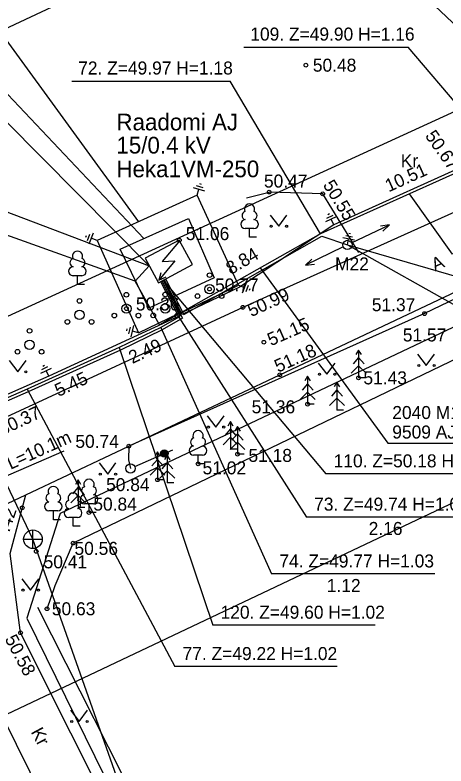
# Model space of a CAD drawing. Extents: x 642747 to 644424, y 6457048 to 6458238.
# Drawn here: x 643688.45 to 643711.66, y 6457504.01 to 6457544.44 of the extents above; entities that cross this region are included whole.
import ezdxf

# ---------------------------------------------------------------- set-up
doc = ezdxf.new("R2010")
doc.units = 0
for name, color, linetype in [('ABIJOONIS', 7, 'Continuous'), ('AED', 7, 'Continuous'), ('HALJASTUS', 7, 'Continuous'), ('HOONE', 7, 'Continuous'), ('JOONSIDE', 7, 'Continuous'), ('KKAEV', 7, 'Continuous'), ('KOORDPUNKT', 7, 'Continuous'), ('KORGUS', 7, 'Continuous'), ('KPKAABEL', 7, 'Continuous'), ('KTRASS', 7, 'Continuous'), ('MOOTPIIR', 7, 'Continuous'), ('MPKAABEL', 7, 'Continuous'), ('MPOHULIIN', 7, 'Continuous'), ('PIIR', 7, 'Continuous'), ('POST', 7, 'Continuous'), ('PUU', 7, 'Continuous'), ('SIOHULIIN', 7, 'Continuous'), ('SITRASS', 7, 'Continuous'), ('TEE', 7, 'Continuous')]:
    doc.layers.add(name, color=color, linetype=linetype)

msp = doc.modelspace()

# ---------------------------------------------------------------- linework, layer by layer
at = {"layer": 'ABIJOONIS'}
for points in [[(643698.673, 6457546.441), (643709.471, 6457546.441), (643717.684, 6457538.68)], [(643677.003, 6457543.321), (643687.801, 6457543.321), (643695.095, 6457533.303)], [(643676.957, 6457540.474), (643687.756, 6457540.474), (643695.388, 6457532.398)], [(643670.945, 6457535.902), (643677.673, 6457535.902), (643685.239, 6457534.889), (643695.681, 6457530.934)], [(643718.109, 6457534.067), (643712.004, 6457531.56), (643709.689, 6457534.812)], [(643706.35, 6457532.056), (643720.437, 6457527.98), (643731.397, 6457527.98)], [(643701.648, 6457530.817), (643708.517, 6457521.392), (643734.485, 6457521.392)], [(643691.073, 6457520.957), (643684.142, 6457517.967), (643682.39, 6457521.311)]]:
    msp.add_lwpolyline(points, dxfattribs=at)
at = {"layer": 'AED'}
for points in [[(643730.468, 6457534.795), (643729.228, 6457534.2), (643722.007, 6457530.651), (643691.577, 6457516.004)], [(643690.171, 6457512.47), (643690.611, 6457513.72), (643691.577, 6457516.004)]]:
    msp.add_lwpolyline(points, dxfattribs=at)
at = {"layer": 'HALJASTUS'}
for p, q in [((643702.185, 6457533.669), (643702.649, 6457533.062)), ((643702.649, 6457533.062), (643703.094, 6457533.669)), ((643710.127, 6457526.179), (643710.591, 6457525.572)), ((643710.591, 6457525.572), (643711.036, 6457526.179)), ((643688.134, 6457525.838), (643688.597, 6457525.231)), ((643688.597, 6457525.231), (643689.043, 6457525.838)), ((643704.779, 6457525.701), (643705.242, 6457525.094)), ((643705.242, 6457525.094), (643705.688, 6457525.701)), ((643698.796, 6457522.862), (643699.26, 6457522.255)), ((643699.26, 6457522.255), (643699.705, 6457522.862)), ((643692.977, 6457520.322), (643693.441, 6457519.716)), ((643693.441, 6457519.716), (643693.886, 6457520.322)), ((643688.815, 6457514.086), (643689.278, 6457513.479)), ((643689.278, 6457513.479), (643689.724, 6457514.086)), ((643691.438, 6457507.006), (643691.901, 6457506.4)), ((643691.901, 6457506.4), (643692.347, 6457507.006))]:
    msp.add_line(p, q, dxfattribs=at)
msp.add_lwpolyline([(643689.657, 6457512.556), (643695.741, 6457500.542), (643701.116, 6457489.232)], dxfattribs=at)
for centre in [(643702.248, 6457533.062), (643703.076, 6457533.062), (643710.19, 6457525.572), (643711.018, 6457525.572), (643689.025, 6457525.231), (643704.841, 6457525.094), (643705.67, 6457525.094), (643698.859, 6457522.255), (643699.687, 6457522.255), (643693.04, 6457519.716), (643693.868, 6457519.716), (643688.877, 6457513.479), (643689.706, 6457513.479), (643691.5, 6457506.4), (643692.329, 6457506.4)]:
    msp.add_circle(centre, 0.055, dxfattribs=at)
at = {"layer": 'HOONE'}
for p, q in [((643697.256, 6457532.202), (643696.375, 6457531.158)), ((643697.059, 6457531.201), (643696.195, 6457530.166)), ((643696.375, 6457531.158), (643697.059, 6457531.201)), ((643696.301, 6457530.548), (643696.195, 6457530.166)), ((643696.195, 6457530.166), (643696.584, 6457530.332))]:
    msp.add_line(p, q, dxfattribs=at)
msp.add_lwpolyline([(643697.295, 6457532.318), (643695.463, 6457531.343), (643696.167, 6457530.021), (643697.999, 6457530.996), (643697.295, 6457532.318)], dxfattribs=at)
at = {"layer": 'KKAEV'}
for p, q in [((643689.411, 6457515.713), (643689.411, 6457516.713)), ((643688.911, 6457516.213), (643689.911, 6457516.213))]:
    msp.add_line(p, q, dxfattribs=at)
msp.add_circle((643689.411, 6457516.213), 0.5, dxfattribs=at)
at = {"layer": 'KOORDPUNKT'}
for p, q in [((643700.769, 6457542.709), (643709.624, 6457542.709)), ((643714.481, 6457536.971), (643709.624, 6457542.709)), ((643691.5, 6457540.883), (643700.04, 6457540.883)), ((643704.897, 6457532.652), (643700.04, 6457540.883)), ((643695.681, 6457530.934), (643687.945, 6457538.712)), ((643694.912, 6457530.116), (643686.074, 6457533.275)), ((643706.35, 6457532.056), (643717.34, 6457525.878)), ((643696.422, 6457530.156), (643705.188, 6457519.734)), ((643697.272, 6457528.173), (643704.137, 6457517.404)), ((643696.304, 6457527.618), (643702.265, 6457514.344)), ((643694.061, 6457526.533), (643699.098, 6457511.586)), ((643689.094, 6457524.29), (643697.052, 6457509.36)), ((643714.042, 6457519.734), (643705.188, 6457519.734)), ((643713.027, 6457517.404), (643704.137, 6457517.404)), ((643711.05, 6457514.344), (643702.265, 6457514.344)), ((643707.847, 6457511.586), (643699.098, 6457511.586)), ((643705.801, 6457509.36), (643697.052, 6457509.36))]:
    msp.add_line(p, q, dxfattribs=at)
for points in [[(643704.897, 6457532.652), (643704.897, 6457532.652), (643704.897, 6457532.652)], [(643706.35, 6457532.056), (643706.35, 6457532.056), (643706.35, 6457532.056)], [(643695.681, 6457530.934), (643695.681, 6457530.934), (643695.681, 6457530.934)], [(643694.912, 6457530.116), (643694.912, 6457530.116), (643694.912, 6457530.116)], [(643696.422, 6457530.156), (643696.422, 6457530.156), (643696.422, 6457530.156)], [(643697.272, 6457528.173), (643697.272, 6457528.173), (643697.272, 6457528.173)], [(643696.304, 6457527.618), (643696.304, 6457527.618), (643696.304, 6457527.618)], [(643689.094, 6457524.29), (643689.094, 6457524.29), (643689.094, 6457524.29)]]:
    msp.add_lwpolyline(points, dxfattribs=at)
at = {"layer": 'KORGUS'}
for centre in [(643704.112, 6457541.735), (643702.139, 6457534.902), (643705.017, 6457534.81), (643697.295, 6457532.318), (643698.926, 6457529.681), (643694.446, 6457528.628), (643700.718, 6457528.698), (643710.503, 6457528.359), (643701.851, 6457526.819), (643702.706, 6457525.068), (643706.952, 6457524.901), (643704.207, 6457523.486), (643694.573, 6457521.224), (643700.433, 6457520.789), (643698.306, 6457520.27), (643696.119, 6457519.414), (643688.838, 6457517.911), (643692.432, 6457517.65), (643691.577, 6457516.004), (643689.59, 6457515.563), (643690.171, 6457512.47), (643688.749, 6457511.18)]:
    msp.add_circle(centre, 0.1, dxfattribs=at)
at = {"layer": 'KPKAABEL'}
for points in [[(643785.796, 6457571.037), (643776.843, 6457566.645), (643770.499, 6457563.796), (643766.764, 6457561.718), (643758.879, 6457558.513), (643750.579, 6457554.536), (643740.363, 6457549.55), (643737.514, 6457548.159), (643731.518, 6457545.231), (643723.365, 6457541.248), (643714.481, 6457536.971), (643704.897, 6457532.652), (643697.084, 6457528.238), (643696.229, 6457527.748), (643694.912, 6457530.116), (643695.681, 6457530.934)], [(643714.481, 6457536.971), (643704.897, 6457532.652)]]:
    msp.add_lwpolyline(points, dxfattribs=at)
at = {"layer": 'KTRASS'}
for points in [[(643689.411, 6457516.213), (643684.182, 6457527.159)], [(643699.268, 6457488.32), (643689.411, 6457516.213)]]:
    msp.add_lwpolyline(points, dxfattribs=at)
at = {"layer": 'MOOTPIIR'}
msp.add_lwpolyline([(643525.446, 6457467.559), (643537.447, 6457435.458), (643944.848, 6457628.51), (644046.626, 6457529.09), (644067.022, 6457529.09), (644138.408, 6457598.401), (644075.1, 6457775.215), (644046.02, 6457752.582), (644092.466, 6457611.94), (644070.657, 6457576.375), (644041.981, 6457570.717), (643942.223, 6457662.862)], close=True, dxfattribs=at)
at = {"layer": 'MPKAABEL'}
for points in [[(643805.865, 6457580.432), (643796.279, 6457575.688), (643787.981, 6457572.136), (643785.733, 6457571.173), (643781.554, 6457569.123), (643776.779, 6457566.78), (643771.586, 6457564.448), (643770.432, 6457563.93), (643766.699, 6457561.854), (643765.114, 6457561.209), (643758.818, 6457558.65), (643756.401, 6457557.492), (643747.057, 6457552.984), (643738.225, 6457548.673), (643729.558, 6457544.44), (643720.951, 6457540.252), (643713.648, 6457536.761), (643705.623, 6457533.144), (643700.531, 6457529.783), (643697.449, 6457528.309), (643696.488, 6457530.191)], [(643698.381, 6457535.365), (643698.477, 6457535.337)], [(643698.04, 6457535.151), (643698.651, 6457534.974)], [(643698.211, 6457535.258), (643698.564, 6457535.155)], [(643698.251, 6457534.737), (643698.346, 6457535.063)], [(643697.399, 6457528.406), (643700.486, 6457529.885), (643698.251, 6457534.737), (643692.871, 6457532.293), (643695.104, 6457527.334), (643697.257, 6457528.362)], [(643705.302, 6457533.699), (643705.392, 6457533.742)], [(643696.83, 6457529.196), (643695.66, 6457528.654), (643694.119, 6457531.823), (643697.789, 6457533.486), (643699.176, 6457530.282), (643696.969, 6457529.26)], [(643705.19, 6457533.312), (643705.763, 6457533.587)], [(643705.246, 6457533.505), (643705.578, 6457533.665)], [(643705.623, 6457533.144), (643705.477, 6457533.45)], [(643692.258, 6457532.48), (643692.294, 6457532.573)], [(643692.348, 6457532.3), (643692.483, 6457532.643)], [(643692.439, 6457532.121), (643692.671, 6457532.713)], [(643696.554, 6457530.227), (643697.534, 6457528.32), (643704.971, 6457532.522), (643706.35, 6457532.056)], [(643706.262, 6457532.571), (643706.624, 6457532.501)], [(643706.422, 6457532.693), (643706.521, 6457532.673)], [(643692.871, 6457532.293), (643692.555, 6457532.417)], [(643706.102, 6457532.449), (643706.726, 6457532.328)], [(643706.35, 6457532.056), (643706.414, 6457532.388)], [(643696.289, 6457530.086), (643697.272, 6457528.173), (643696.304, 6457527.618), (643694.061, 6457526.533), (643689.094, 6457524.29), (643679.887, 6457520.261), (643679.223, 6457519.895), (643675.996, 6457516.951), (643671.564, 6457514.815), (643667.06, 6457512.644), (643660.451, 6457509.256), (643649.68, 6457503.955), (643643.889, 6457501.235), (643639.182, 6457499.025), (643631.014, 6457495.189), (643626.472, 6457494.72), (643614.163, 6457489.443), (643609.518, 6457487.318), (643592.691, 6457479.179)], [(643696.355, 6457530.121), (643697.317, 6457528.246), (643690.265, 6457524.984), (643679.821, 6457520.397), (643679.135, 6457520.018), (643675.911, 6457517.077), (643666.993, 6457512.779), (643662.055, 6457510.248), (643650.319, 6457504.437)], [(643696.422, 6457530.156), (643697.471, 6457528.114), (643696.379, 6457527.488), (643694.13, 6457526.399), (643689.156, 6457524.153), (643679.925, 6457520.115), (643679.597, 6457519.088)], [(643700.486, 6457529.885), (643700.802, 6457529.762)], [(643700.917, 6457530.058), (643700.687, 6457529.466)], [(643701.009, 6457529.879), (643700.875, 6457529.536)], [(643701.1, 6457529.7), (643701.063, 6457529.607)], [(643694.699, 6457527.106), (643694.851, 6457527.724)], [(643694.472, 6457527.438), (643694.496, 6457527.535)], [(643694.586, 6457527.272), (643694.673, 6457527.629)], [(643695.104, 6457527.334), (643694.775, 6457527.415)], [(643689.831, 6457525.152), (643690.405, 6457525.427)], [(643689.887, 6457525.345), (643690.219, 6457525.505)], [(643689.943, 6457525.539), (643690.033, 6457525.582)], [(643690.265, 6457524.984), (643690.118, 6457525.29)], [(643689.094, 6457524.29), (643679.887, 6457520.261)], [(643689.156, 6457524.153), (643679.925, 6457520.115)]]:
    msp.add_lwpolyline(points, dxfattribs=at)
at = {"layer": 'MPOHULIIN'}
for p, q in [((643706.575, 6457532.163), (643708.607, 6457533.131)), ((643708.607, 6457533.131), (643708.135, 6457533.073)), ((643708.607, 6457533.131), (643708.263, 6457532.803)), ((643706.125, 6457531.947), (643704.099, 6457530.968)), ((643704.099, 6457530.968), (643704.441, 6457531.298)), ((643704.099, 6457530.968), (643704.57, 6457531.029))]:
    msp.add_line(p, q, dxfattribs=at)
at = {"layer": 'PIIR'}
for points in [[(643807.33, 6457582.88), (643742.37, 6457711.12), (643680.23, 6457682.19), (643708.95, 6457623.53), (643648.6, 6457595.3), (643683.74, 6457526.24)], [(643750.22, 6457457.29), (643778.12, 6457470.27), (643782.64, 6457472.43), (643747.54, 6457544.43), (643690.88, 6457517.6), (643689.08, 6457511.97), (643715.74, 6457457.75), (643719.34, 6457459.43), (643726.21, 6457446.01)]]:
    msp.add_lwpolyline(points, close=True, dxfattribs=at)
at = {"layer": 'POST'}
for centre in [(643706.35, 6457532.056), (643694.666, 6457520.025)]:
    msp.add_circle(centre, 0.25, dxfattribs=at)
at = {"layer": 'PUU'}
for p, q in [((643701.317, 6457532.943), (643700.837, 6457532.943)), ((643701.077, 6457532.468), (643701.077, 6457532.943)), ((643701.457, 6457532.468), (643701.077, 6457532.468)), ((643692.05, 6457530.403), (643691.57, 6457530.403)), ((643691.81, 6457529.928), (643691.81, 6457530.403)), ((643692.19, 6457529.928), (643691.81, 6457529.928)), ((643706.952, 6457526.401), (643706.802, 6457526.151)), ((643707.102, 6457526.151), (643706.952, 6457526.401)), ((643706.952, 6457526.401), (643706.952, 6457524.901)), ((643706.952, 6457526.001), (643706.652, 6457525.651)), ((643707.252, 6457525.651), (643706.952, 6457526.001)), ((643706.952, 6457525.551), (643706.552, 6457525.151)), ((643707.352, 6457525.151), (643706.952, 6457525.551)), ((643704.207, 6457524.986), (643704.057, 6457524.736)), ((643704.357, 6457524.736), (643704.207, 6457524.986)), ((643704.207, 6457524.986), (643704.207, 6457523.486)), ((643707.312, 6457524.901), (643706.952, 6457524.901)), ((643704.207, 6457524.586), (643703.907, 6457524.236)), ((643704.507, 6457524.236), (643704.207, 6457524.586)), ((643705.784, 6457524.661), (643705.634, 6457524.411)), ((643705.934, 6457524.411), (643705.784, 6457524.661)), ((643705.784, 6457524.661), (643705.784, 6457523.161)), ((643704.207, 6457524.136), (643703.807, 6457523.736)), ((643704.607, 6457523.736), (643704.207, 6457524.136)), ((643705.784, 6457524.261), (643705.484, 6457523.911)), ((643706.084, 6457523.911), (643705.784, 6457524.261)), ((643705.784, 6457523.811), (643705.384, 6457523.411)), ((643706.184, 6457523.411), (643705.784, 6457523.811)), ((643704.567, 6457523.486), (643704.207, 6457523.486)), ((643706.144, 6457523.161), (643705.784, 6457523.161)), ((643700.053, 6457522.554), (643699.903, 6457522.304)), ((643700.203, 6457522.304), (643700.053, 6457522.554)), ((643700.053, 6457522.554), (643700.053, 6457521.054)), ((643700.053, 6457522.154), (643699.753, 6457521.804)), ((643700.353, 6457521.804), (643700.053, 6457522.154)), ((643700.433, 6457522.289), (643700.283, 6457522.039)), ((643700.583, 6457522.039), (643700.433, 6457522.289)), ((643700.433, 6457522.289), (643700.433, 6457520.789)), ((643700.053, 6457521.704), (643699.653, 6457521.304)), ((643700.453, 6457521.304), (643700.053, 6457521.704)), ((643700.433, 6457521.889), (643700.133, 6457521.539)), ((643700.733, 6457521.539), (643700.433, 6457521.889)), ((643700.433, 6457521.439), (643700.033, 6457521.039)), ((643700.833, 6457521.039), (643700.433, 6457521.439)), ((643696.119, 6457520.914), (643695.969, 6457520.664)), ((643696.269, 6457520.664), (643696.119, 6457520.914)), ((643696.119, 6457520.914), (643696.119, 6457519.414)), ((643700.413, 6457521.054), (643700.053, 6457521.054)), ((643700.793, 6457520.789), (643700.433, 6457520.789)), ((643696.119, 6457520.514), (643695.819, 6457520.164)), ((643696.419, 6457520.164), (643696.119, 6457520.514)), ((643696.646, 6457520.747), (643696.496, 6457520.497)), ((643696.796, 6457520.497), (643696.646, 6457520.747)), ((643696.646, 6457520.747), (643696.646, 6457519.247)), ((643698.546, 6457520.745), (643698.066, 6457520.745)), ((643698.306, 6457520.27), (643698.306, 6457520.745)), ((643696.119, 6457520.064), (643695.719, 6457519.664)), ((643696.519, 6457519.664), (643696.119, 6457520.064)), ((643696.646, 6457520.347), (643696.346, 6457519.997)), ((643696.946, 6457519.997), (643696.646, 6457520.347)), ((643698.686, 6457520.27), (643698.306, 6457520.27)), ((643696.646, 6457519.897), (643696.246, 6457519.497)), ((643697.046, 6457519.497), (643696.646, 6457519.897)), ((643691.848, 6457519.415), (643691.698, 6457519.165)), ((643691.998, 6457519.165), (643691.848, 6457519.415)), ((643691.848, 6457519.415), (643691.848, 6457517.915)), ((643696.479, 6457519.414), (643696.119, 6457519.414)), ((643697.006, 6457519.247), (643696.646, 6457519.247)), ((643691.848, 6457519.015), (643691.548, 6457518.665)), ((643692.148, 6457518.665), (643691.848, 6457519.015)), ((643691.848, 6457518.565), (643691.448, 6457518.165)), ((643692.248, 6457518.165), (643691.848, 6457518.565)), ((643692.672, 6457518.125), (643692.192, 6457518.125)), ((643692.432, 6457517.65), (643692.432, 6457518.125)), ((643690.752, 6457517.736), (643690.272, 6457517.736)), ((643690.512, 6457517.261), (643690.512, 6457517.736)), ((643692.208, 6457517.915), (643691.848, 6457517.915)), ((643692.812, 6457517.65), (643692.432, 6457517.65)), ((643690.892, 6457517.261), (643690.512, 6457517.261)), ((643691.819, 6457517.388), (643691.339, 6457517.388)), ((643691.579, 6457516.913), (643691.579, 6457517.388)), ((643691.959, 6457516.913), (643691.579, 6457516.913))]:
    msp.add_line(p, q, dxfattribs=at)
for centre, radius in [((643698.926, 6457530.431), 0.125), ((643698.926, 6457529.681), 0.25), ((643694.446, 6457529.378), 0.125), ((643696.54, 6457529.391), 0.125), ((643698.276, 6457529.306), 0.125), ((643699.576, 6457529.306), 0.125), ((643691.919, 6457529.041), 0.125), ((643694.446, 6457528.628), 0.25), ((643696.54, 6457528.641), 0.25), ((643691.919, 6457528.291), 0.25), ((643693.796, 6457528.253), 0.125), ((643695.096, 6457528.253), 0.125), ((643695.89, 6457528.266), 0.125), ((643697.19, 6457528.266), 0.125), ((643691.269, 6457527.916), 0.125), ((643692.569, 6457527.916), 0.125), ((643689.231, 6457527.432), 0.125), ((643689.231, 6457526.682), 0.25), ((643688.581, 6457526.307), 0.125), ((643689.881, 6457526.307), 0.125)]:
    msp.add_circle(centre, radius, dxfattribs=at)
for centre, radius, start, end in [((643701.077, 6457533.988), 0.277, 332.5799, 207.4201), ((643700.907, 6457533.641), 0.233, 109.0217, 253.1415), ((643701.247, 6457533.641), 0.233, 286.8508, 70.9859), ((643700.84, 6457533.18), 0.238, 90.0016, 269.3953), ((643701.314, 6457533.18), 0.238, 270.6047, 89.9984), ((643691.81, 6457531.448), 0.277, 332.5799, 207.4201), ((643691.64, 6457531.101), 0.233, 109.0217, 253.1415), ((643691.98, 6457531.101), 0.233, 286.8508, 70.9859), ((643691.573, 6457530.64), 0.238, 90.0016, 269.3953), ((643692.047, 6457530.64), 0.238, 270.6047, 89.9984), ((643698.306, 6457521.79), 0.277, 332.5799, 207.4201), ((643698.136, 6457521.443), 0.233, 109.0217, 253.1415), ((643698.476, 6457521.443), 0.233, 286.8508, 70.9859), ((643698.068, 6457520.983), 0.238, 90.0016, 269.3953), ((643698.543, 6457520.983), 0.238, 270.6047, 89.9984), ((643692.432, 6457519.17), 0.277, 332.5799, 207.4201), ((643690.512, 6457518.781), 0.277, 332.5799, 207.4201), ((643692.262, 6457518.822), 0.233, 109.0217, 253.1415), ((643692.602, 6457518.822), 0.233, 286.8508, 70.9859), ((643690.342, 6457518.433), 0.233, 109.0217, 253.1415), ((643690.682, 6457518.433), 0.233, 286.8508, 70.9859), ((643691.579, 6457518.433), 0.277, 332.5799, 207.4201), ((643692.194, 6457518.362), 0.238, 90.0016, 269.3953), ((643692.669, 6457518.362), 0.238, 270.6047, 89.9984), ((643690.275, 6457517.973), 0.238, 90.0016, 269.3953), ((643690.75, 6457517.973), 0.238, 270.6047, 89.9984), ((643691.408, 6457518.086), 0.233, 109.0217, 253.1415), ((643691.749, 6457518.086), 0.233, 286.8508, 70.9859), ((643691.341, 6457517.626), 0.238, 90.0016, 269.3953), ((643691.816, 6457517.626), 0.238, 270.6047, 89.9984)]:
    msp.add_arc(centre, radius, start, end, dxfattribs=at)
at = {"layer": 'SIOHULIIN'}
msp.add_line((643694.894, 6457520.126), (643696.943, 6457521.035), dxfattribs=at)
for radius in [0.199, 0.19, 0.18, 0.171, 0.162, 0.152, 0.143, 0.133, 0.124, 0.114, 0.105, 0.0953, 0.0858, 0.0763, 0.0669, 0.0574, 0.0479, 0.0385, 0.029, 0.0195, 0.0101, 0.00061]:
    msp.add_circle((643696.489, 6457520.834), radius, dxfattribs=at)
at = {"layer": 'SITRASS'}
msp.add_lwpolyline([(643814.156, 6457570.25), (643811.349, 6457574.393), (643810.727, 6457574.717), (643809.889, 6457574.858), (643799.015, 6457570.178), (643785.395, 6457563.561), (643775.068, 6457558.5), (643760.375, 6457551.627), (643746.716, 6457545.631), (643746.704, 6457544.802), (643746.702, 6457544.799), (643746.829, 6457544.323), (643746.616, 6457545.538), (643724.743, 6457535.187), (643710.503, 6457528.359), (643694.573, 6457521.224), (643694.552, 6457520.484), (643694.666, 6457520.025)], dxfattribs=at)
at = {"layer": 'TEE'}
for points in [[(643746.591, 6457574.314), (643732.424, 6457566.763), (643729.066, 6457563.602), (643728.503, 6457561.602), (643729.059, 6457559.069), (643729.831, 6457555.645), (643731.562, 6457550.831), (643732.565, 6457544.016), (643730.855, 6457542.193), (643718.254, 6457535.466), (643716.466, 6457535.771), (643700.718, 6457528.698), (643687.218, 6457522.442), (643684.591, 6457521.627), (643681.939, 6457519.998), (643680.882, 6457518.056), (643662.455, 6457508.936), (643645.195, 6457501.166), (643628.832, 6457493.712), (643613.742, 6457486.52), (643600.86, 6457480.184)], [(643601.811, 6457477.818), (643614.888, 6457484.225), (643629.926, 6457491.355), (643646.627, 6457498.988), (643663.305, 6457506.521), (643682.169, 6457515.373), (643702.706, 6457525.068), (643719.451, 6457532.981), (643744.189, 6457544.886), (643760.109, 6457552.753), (643794.075, 6457568.819)], [(643700.922, 6457534.585), (643702.139, 6457534.902)], [(643706.958, 6457531.651), (643705.017, 6457534.81), (643702.139, 6457534.902)], [(643700.146, 6457488.754), (643694.164, 6457500.367), (643688.749, 6457511.18), (643688.186, 6457515.45), (643689.023, 6457518.609)], [(643697.728, 6457487.561), (643691.515, 6457499.131), (643686.266, 6457509.7), (643684.68, 6457514.253), (643682.941, 6457515.576)]]:
    msp.add_lwpolyline(points, dxfattribs=at)

# ---------------------------------------------------------------- texts
at = {"layer": 'ABIJOONIS'}
for s, p in [('2040 M10-AJ Raadomi AHXAMK-W 3x120+35 24kV L=659.8m', (643708.765, 6457522.686)), ('9509 AJ Raadomi-M22 AXPK 4G120 L=12.1m', (643708.765, 6457521.635))]:
    msp.add_text(s, height=0.7, dxfattribs=at).set_placement(p)
msp.add_text('2x110 PL L=10.1m', height=0.7, rotation=24.3052, dxfattribs=at).set_placement((643684.364, 6457518.214))
at = {"layer": 'HOONE'}
for s, p in [('Raadomi AJ', (643693.907, 6457538.225)), ('15/0.4 kV', (643693.907, 6457536.979)), ('Heka1VM-250', (643693.907, 6457535.7))]:
    msp.add_text(s, height=0.9, dxfattribs=at).set_placement(p)
at = {"layer": 'JOONSIDE'}
for s, rotation, p in [('10.51', 24.2585, (643708.573, 6457534.887)), ('8.84', 30.4312, (643700.07, 6457530.433)), ('2.49', 24.7762, (643694.765, 6457525.646)), ('5.45', 24.7762, (643690.786, 6457523.871))]:
    msp.add_text(s, height=0.7, rotation=rotation, dxfattribs=at).set_placement(p)
for s, p in [('2.16', (643707.494, 6457516.444)), ('1.12', (643705.239, 6457513.374))]:
    msp.add_text(s, height=0.7, dxfattribs=at).set_placement(p)
at = {"layer": 'KOORDPUNKT'}
for s, p in [('109. Z=49.90 H=1.16', (643701.119, 6457543.059)), ('72. Z=49.97 H=1.18', (643691.85, 6457541.233)), ('110. Z=50.18 H=0.86', (643705.608, 6457520.084)), ('73. Z=49.74 H=1.04', (643704.557, 6457517.754)), ('74. Z=49.77 H=1.03', (643702.685, 6457514.694)), ('120. Z=49.60 H=1.02', (643699.518, 6457511.936)), ('77. Z=49.22 H=1.02', (643697.472, 6457509.71))]:
    msp.add_text(s, height=0.7, dxfattribs=at).set_placement(p)
at = {"layer": 'KORGUS'}
for s, p in [('50.48', (643704.487, 6457541.385)), (' 50.47', (643701.593, 6457535.147)), ('51.06', (643697.645, 6457532.318)), (' 50.77', (643698.962, 6457529.554)), (' 50.36', (643694.696, 6457528.528)), (' 51.37', (643707.403, 6457528.491)), (' 51.57', (643709.072, 6457526.861)), (' 51.43', (643706.952, 6457524.551)), (' 51.36', (643700.932, 6457522.992)), (' 50.74', (643691.438, 6457521.133)), (' 51.18', (643700.76, 6457520.377)), (' 51.02', (643698.29, 6457519.707)), (' 50.84', (643693.094, 6457518.803)), (' 50.84', (643692.405, 6457517.755)), (' 50.56', (643691.39, 6457515.373)), (' 50.41', (643689.728, 6457514.647)), (' 50.63', (643690.171, 6457512.12))]:
    msp.add_text(s, height=0.7, dxfattribs=at).set_placement(p)
for s, rotation, p in [(' 50.67', 305.271, (643710.353, 6457538.138)), (' 50.55', 301.4893, (643704.872, 6457535.513)), (' 50.99', 24.6488, (643700.937, 6457528.058)), (' 51.15', 23.5958, (643701.991, 6457526.498)), (' 51.18', 24.0431, (643702.375, 6457525.067)), (' 50.37', 25.1722, (643687.537, 6457521.673)), (' 50.42', 71.4344, (643687.718, 6457515.324)), (' 50.58', 298.02, (643687.754, 6457511.079))]:
    msp.add_text(s, height=0.7, rotation=rotation, dxfattribs=at).set_placement(p)
at = {"layer": 'POST'}
msp.add_text('M22', height=0.7, dxfattribs=at).set_placement((643705.683, 6457530.685))
at = {"layer": 'TEE'}
msp.add_text('Kr', height=0.7, dxfattribs=at).set_placement((643709.221, 6457536.237))
for s, rotation, p in [('A', 24.1341, (643711.065, 6457530.632)), ('Kr', 298.2382, (643689.28, 6457505.844))]:
    msp.add_text(s, height=0.7, rotation=rotation, dxfattribs=at).set_placement(p)

doc.saveas('drawing.dxf')
